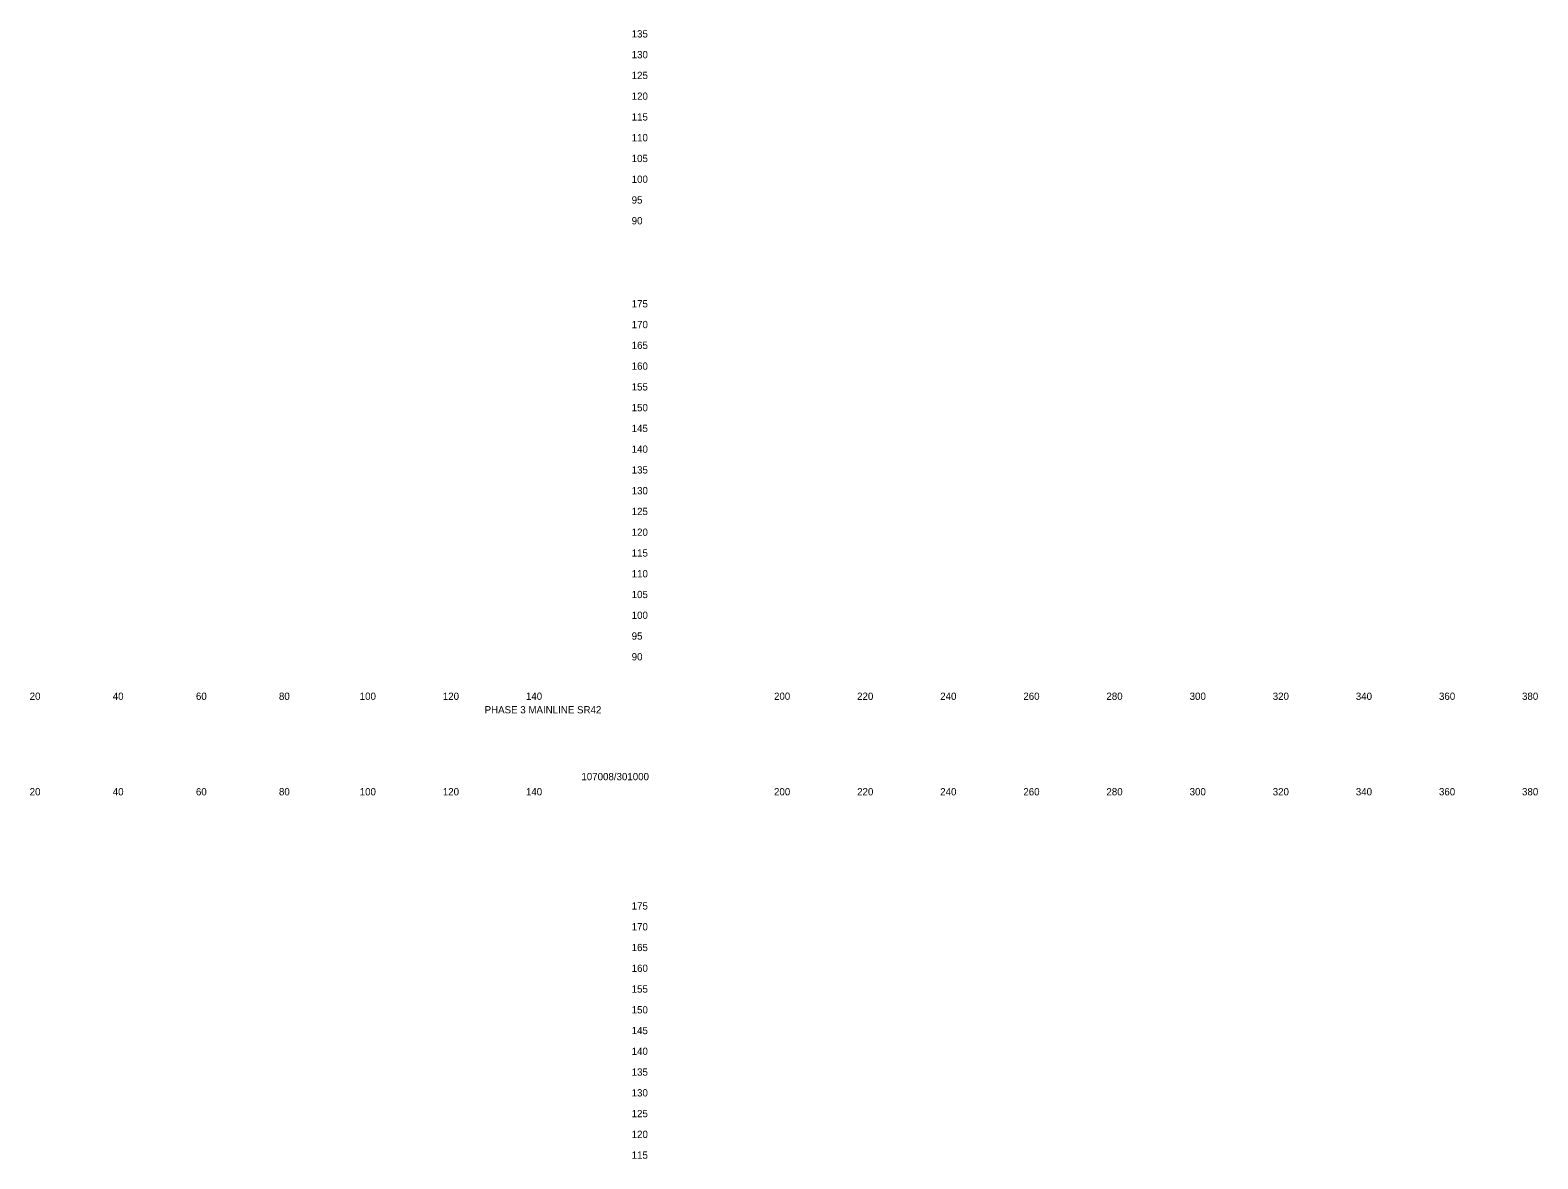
# Model space of a CAD drawing. Extents: x 21281 to 22024, y 6472 to 15198.
# Drawn here: x 21661.4 to 22024.2, y 11654.8 to 11926.6 of the extents above; entities that cross this region are included whole.
import ezdxf

# ---------------------------------------------------------------- set-up
doc = ezdxf.new("R2010")
doc.units = 0
doc.layers.add('Draft_XS_Grid', color=7, linetype='Continuous')
doc.layers.add('Draft_XS_Text', color=7, linetype='Continuous')

msp = doc.modelspace()

# ---------------------------------------------------------------- texts
at = {"layer": 'Draft_XS_Grid'}
for s, p in [('  135  ', (21804.84, 11924.84)), ('  130  ', (21804.84, 11919.84)), ('  125  ', (21804.84, 11914.84)), ('  120  ', (21804.84, 11909.84)), ('  115  ', (21804.84, 11904.84)), ('  110  ', (21804.84, 11899.84)), ('  105  ', (21804.84, 11894.84)), ('  100  ', (21804.84, 11889.84)), ('  95  ', (21804.84, 11884.84)), ('  90  ', (21804.84, 11879.84)), ('  175  ', (21804.84, 11859.84)), ('  170  ', (21804.84, 11854.84)), ('  165  ', (21804.84, 11849.84)), ('  160  ', (21804.84, 11844.84)), ('  155  ', (21804.84, 11839.84)), ('  150  ', (21804.84, 11834.84)), ('  145  ', (21804.84, 11829.84)), ('  140  ', (21804.84, 11824.84)), ('  135  ', (21804.84, 11819.84)), ('  130  ', (21804.84, 11814.84)), ('  125  ', (21804.84, 11809.84)), ('  120  ', (21804.84, 11804.84)), ('  115  ', (21804.84, 11799.84)), ('  110  ', (21804.84, 11794.84)), ('  105  ', (21804.84, 11789.84)), ('  100  ', (21804.84, 11784.84)), ('  95  ', (21804.84, 11779.84)), ('  90  ', (21804.84, 11774.84)), ('  175  ', (21804.84, 11714.84)), ('  170  ', (21804.84, 11709.84)), ('  165  ', (21804.84, 11704.84)), ('  160  ', (21804.84, 11699.84)), ('  155  ', (21804.84, 11694.84)), ('  150  ', (21804.84, 11689.84)), ('  145  ', (21804.84, 11684.84)), ('  140  ', (21804.84, 11679.84)), ('  135  ', (21804.84, 11674.84)), ('  130  ', (21804.84, 11669.84)), ('  125  ', (21804.84, 11664.84)), ('  120  ', (21804.84, 11659.84)), ('  115  ', (21804.84, 11654.84))]:
    msp.add_text(s, height=1.75, dxfattribs=at).set_placement(p)
at = {"layer": 'Draft_XS_Text'}
for s, p in [('  20  ', (21659.95, 11765.34)), ('  40  ', (21679.95, 11765.34)), ('  60  ', (21699.97, 11765.34)), ('  80  ', (21719.95, 11765.34)), ('  100  ', (21739.39, 11765.34)), ('  120  ', (21759.39, 11765.34)), ('  140  ', (21779.39, 11765.34)), ('  200  ', (21839.1, 11765.34)), ('  220  ', (21859.1, 11765.34)), ('  240  ', (21879.1, 11765.34)), ('  260  ', (21899.11, 11765.34)), ('  280  ', (21919.1, 11765.34)), ('  300  ', (21939.13, 11765.34)), ('  320  ', (21959.13, 11765.34)), ('  340  ', (21979.13, 11765.34)), ('  360  ', (21999.14, 11765.34)), ('  380  ', (22019.13, 11765.34)), ('PHASE 3 MAINLINE SR42', (21770.75, 11762.08)), ('107008/301000', (21794.04, 11745.99)), ('  20  ', (21659.95, 11742.34)), ('  40  ', (21679.95, 11742.34)), ('  60  ', (21699.97, 11742.34)), ('  80  ', (21719.95, 11742.34)), ('  100  ', (21739.39, 11742.34)), ('  120  ', (21759.39, 11742.34)), ('  140  ', (21779.39, 11742.34)), ('  200  ', (21839.1, 11742.34)), ('  220  ', (21859.1, 11742.34)), ('  240  ', (21879.1, 11742.34)), ('  260  ', (21899.11, 11742.34)), ('  280  ', (21919.1, 11742.34)), ('  300  ', (21939.13, 11742.34)), ('  320  ', (21959.13, 11742.34)), ('  340  ', (21979.13, 11742.34)), ('  360  ', (21999.14, 11742.34)), ('  380  ', (22019.13, 11742.34))]:
    msp.add_text(s, height=1.75, dxfattribs=at).set_placement(p)

doc.saveas('drawing.dxf')
